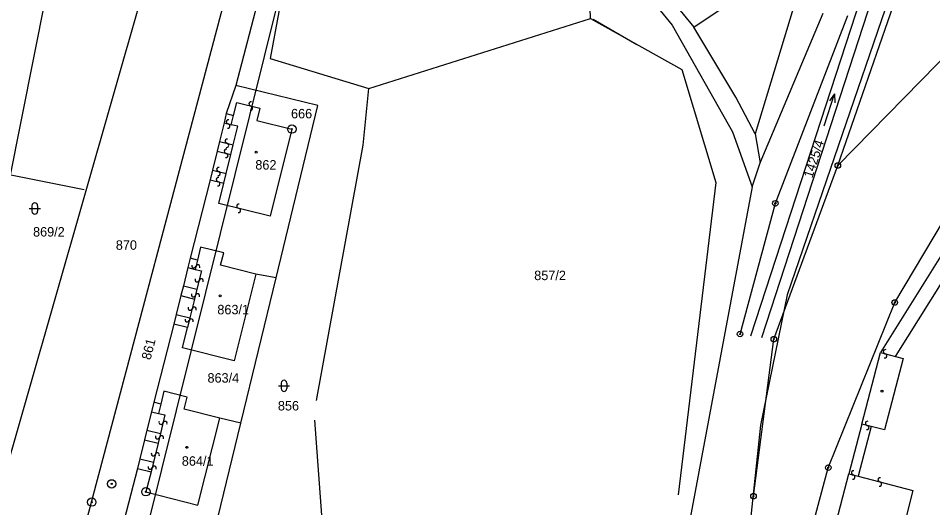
# Model space of a CAD drawing. Extents: x -469926 to -462499, y -1098642 to -1092733.
# Drawn here: x -465754.8 to -465590.7, y -1094948.2 to -1094860.4 of the extents above; entities that cross this region are included whole.
import ezdxf

# ---------------------------------------------------------------- set-up
doc = ezdxf.new("R2010")
doc.units = 0
for name, color, linetype in [('Vrstva 1', 7, 'Continuous'), ('Vrstva 14', 7, 'Continuous'), ('Vrstva 24', 7, 'Continuous'), ('Vrstva 25', 7, 'Continuous'), ('Vrstva 27', 7, 'Continuous'), ('Vrstva 4', 7, 'Continuous'), ('Vrstva 50', 7, 'Continuous'), ('Vrstva 51', 7, 'Continuous'), ('Vrstva 6', 7, 'Continuous'), ('Vrstva 63', 7, 'Continuous')]:
    doc.layers.add(name, color=color, linetype=linetype)

msp = doc.modelspace()

# ---------------------------------------------------------------- linework, layer by layer
at = {"layer": 'Vrstva 1'}
for p, q in [((-465698.22, -1094805.73), (-465715.79, -1094872.42)), ((-465698.22, -1094805.73), (-465709.61, -1094867.57)), ((-465705.26, -1094809.85), (-465747.5, -1094968.95)), ((-465774.7, -1094981.18), (-465741.64, -1094815.03)), ((-465727.35, -1094837.65), (-465765.18, -1094969.7)), ((-465652.11, -1094860.36), (-465652.54, -1094842.94)), ((-465652.54, -1094842.94), (-465637.41, -1094861.6)), ((-465648.71, -1094843.31), (-465633.53, -1094861.97)), ((-465607.69, -1094886.76), (-465568.94, -1094847.26)), ((-465613.05, -1094849.65), (-465622.51, -1094881.1)), ((-465607.69, -1094886.76), (-465595.39, -1094851.35)), ((-465633.53, -1094861.97), (-465624.18, -1094855.62)), ((-465621.65, -1094886.26), (-465610.33, -1094859.42)), ((-465691.88, -1094872.95), (-465652.11, -1094860.36)), ((-465652.11, -1094860.36), (-465635.72, -1094869.53)), ((-465618.91, -1094893.55), (-465605.92, -1094859.84)), ((-465637.41, -1094861.6), (-465626.59, -1094880.71)), ((-465626, -1094874.53), (-465633.53, -1094861.97)), ((-465709.61, -1094867.57), (-465691.88, -1094872.95)), ((-465635.72, -1094869.53), (-465629.58, -1094889.81)), ((-465715.79, -1094872.42), (-465717.48, -1094877.46)), ((-465701.04, -1094876), (-465715.79, -1094872.42)), ((-465692.94, -1094883.14), (-465691.88, -1094872.95)), ((-465692.94, -1094883.14), (-465691.88, -1094872.95)), ((-465622.51, -1094881.1), (-465626, -1094874.53)), ((-465717.48, -1094877.46), (-465717.88, -1094879.14)), ((-465708.56, -1094906.93), (-465701.04, -1094876)), ((-465717.88, -1094879.14), (-465718.69, -1094882.45)), ((-465626.59, -1094880.71), (-465623.08, -1094890.59)), ((-465718.69, -1094882.45), (-465719.12, -1094884.2)), ((-465622.51, -1094881.1), (-465621.65, -1094886.26)), ((-465701.3, -1094928.96), (-465692.94, -1094883.14)), ((-465719.12, -1094884.2), (-465719.94, -1094887.59)), ((-465619.18, -1094917.94), (-465607.69, -1094886.76)), ((-465719.94, -1094887.59), (-465720.36, -1094889.33)), ((-465720.36, -1094889.33), (-465723.95, -1094903.41)), ((-465629.58, -1094889.81), (-465636.35, -1094945.88)), ((-465623.08, -1094890.59), (-465634.59, -1094952.18)), ((-465597.47, -1094911.35), (-465584.24, -1094889.14)), ((-465625.24, -1094917.01), (-465618.91, -1094893.55)), ((-465722.1, -1094901.44), (-465722.66, -1094903.73)), ((-465717.95, -1094902.44), (-465722.1, -1094901.44)), ((-465723.95, -1094903.41), (-465724.37, -1094905.08)), ((-465722.66, -1094903.73), (-465723.95, -1094903.41)), ((-465718.51, -1094904.64), (-465717.95, -1094902.44)), ((-465724.37, -1094905.08), (-465725.19, -1094908.38)), ((-465712.19, -1094906.26), (-465718.51, -1094904.64)), ((-465712.19, -1094906.26), (-465716.1, -1094921.83)), ((-465714.9, -1094933.02), (-465708.56, -1094906.93)), ((-465708.56, -1094906.93), (-465712.19, -1094906.26)), ((-465725.19, -1094908.38), (-465725.62, -1094910.12)), ((-465725.62, -1094910.12), (-465726.46, -1094913.49)), ((-465609.41, -1094941), (-465597.47, -1094911.35)), ((-465726.46, -1094913.49), (-465726.89, -1094915.23)), ((-465726.89, -1094915.23), (-465730.52, -1094929.27)), ((-465724.46, -1094915.83), (-465726.89, -1094915.23)), ((-465725.37, -1094919.47), (-465724.46, -1094915.83)), ((-465622.83, -1094946.11), (-465619.18, -1094917.94)), ((-465716.1, -1094921.83), (-465725.37, -1094919.47)), ((-465728.67, -1094927.29), (-465729.25, -1094929.58)), ((-465724.52, -1094928.32), (-465728.67, -1094927.29)), ((-465725.06, -1094930.52), (-465724.52, -1094928.32)), ((-465730.52, -1094929.27), (-465730.93, -1094930.95)), ((-465729.25, -1094929.58), (-465730.52, -1094929.27)), ((-465730.93, -1094930.95), (-465731.73, -1094934.27)), ((-465718.67, -1094932.13), (-465725.06, -1094930.52)), ((-465722.6, -1094947.71), (-465718.67, -1094932.13)), ((-465721.21, -1094959.01), (-465714.9, -1094933.02)), ((-465714.9, -1094933.02), (-465718.67, -1094932.13)), ((-465698.71, -1094971.07), (-465701.56, -1094932.5)), ((-465731.73, -1094934.27), (-465732.16, -1094936.02)), ((-465732.16, -1094936.02), (-465732.98, -1094939.4)), ((-465732.98, -1094939.4), (-465733.4, -1094941.14)), ((-465733.4, -1094941.14), (-465737.05, -1094955.16)), ((-465733.4, -1094941.14), (-465730.97, -1094941.73)), ((-465613.36, -1094955.68), (-465609.41, -1094941)), ((-465730.97, -1094941.73), (-465731.92, -1094945.33)), ((-465731.92, -1094945.33), (-465722.6, -1094947.71))]:
    msp.add_line(p, q, dxfattribs=at)
at = {"layer": 'Vrstva 14'}
msp.add_line((-465687.49, -1094773.7), (-465736.67, -1094971.8), dxfattribs=at)
at = {"layer": 'Vrstva 24'}
for centre, radius in [((-465705.7, -1094880.23), 0.75), ((-465705.7, -1094880.23), 0.1), ((-465607.69, -1094886.76), 0.5), ((-465607.69, -1094886.76), 0.1), ((-465618.91, -1094893.55), 0.5), ((-465618.91, -1094893.55), 0.1), ((-465597.47, -1094911.35), 0.5), ((-465597.47, -1094911.35), 0.1), ((-465625.24, -1094917.01), 0.5), ((-465625.24, -1094917.01), 0.1), ((-465619.18, -1094917.94), 0.5), ((-465619.18, -1094917.94), 0.1), ((-465609.41, -1094941), 0.5), ((-465609.41, -1094941), 0.1), ((-465738.06, -1094943.9), 0.75), ((-465738.06, -1094943.9), 0.1), ((-465731.92, -1094945.33), 0.75), ((-465741.64, -1094947.18), 0.75), ((-465731.92, -1094945.33), 0.1), ((-465622.83, -1094946.11), 0.5), ((-465622.83, -1094946.11), 0.1), ((-465741.64, -1094947.18), 0.1)]:
    msp.add_circle(centre, radius, dxfattribs=at)
at = {"layer": 'Vrstva 25'}
for p, q in [((-465752.37, -1094893.98), (-465752.37, -1094894.98)), ((-465751.37, -1094893.98), (-465751.37, -1094894.98)), ((-465752.87, -1094894.48), (-465750.87, -1094894.48)), ((-465708.12, -1094926.31), (-465706.12, -1094926.31)), ((-465707.62, -1094925.81), (-465707.62, -1094926.81)), ((-465706.62, -1094925.81), (-465706.62, -1094926.81))]:
    msp.add_line(p, q, dxfattribs=at)
for points in [[(-465610.12, -1094879.62), (-465608.26, -1094873.92), (-465609.2, -1094875.19)], [(-465608.26, -1094873.92), (-465608.25, -1094875.5)]]:
    msp.add_lwpolyline(points, dxfattribs=at)
for centre in [(-465712.1, -1094884.35), (-465718.59, -1094910.17), (-465599.76, -1094927.27), (-465724.59, -1094937.35)]:
    msp.add_circle(centre, 0.175, dxfattribs=at)
for centre, start, end in [((-465751.87, -1094893.98), 0, 180), ((-465751.87, -1094894.98), 180, 0), ((-465707.12, -1094925.81), 0, 180), ((-465707.12, -1094926.81), 180, 0)]:
    msp.add_arc(centre, 0.5, start, end, dxfattribs=at)
at = {"layer": 'Vrstva 27'}
msp.add_lwpolyline([(-465743.02, -1094891.12), (-465797.45, -1094880.27)], dxfattribs=at)
at = {"layer": 'Vrstva 4'}
for p, q in [((-465623.29, -1094917.31), (-465601.6, -1094850.75)), ((-465621.33, -1094917.61), (-465599.61, -1094850.95)), ((-465716.18, -1094877.77), (-465715.62, -1094875.48)), ((-465715.62, -1094875.48), (-465711.46, -1094876.49)), ((-465717.48, -1094877.46), (-465716.18, -1094877.77)), ((-465711.46, -1094876.49), (-465712.02, -1094878.67)), ((-465717.88, -1094879.14), (-465716.59, -1094879.46)), ((-465716.59, -1094879.46), (-465716.18, -1094877.77)), ((-465712.02, -1094878.67), (-465705.7, -1094880.23)), ((-465715.44, -1094879.73), (-465716.59, -1094879.46)), ((-465716.25, -1094883.05), (-465715.44, -1094879.73)), ((-465705.7, -1094880.23), (-465709.59, -1094895.87)), ((-465718.69, -1094882.45), (-465716.25, -1094883.05)), ((-465716.67, -1094884.8), (-465716.25, -1094883.05)), ((-465719.12, -1094884.2), (-465716.67, -1094884.8)), ((-465717.5, -1094888.18), (-465716.67, -1094884.8)), ((-465623.08, -1094890.59), (-465621.65, -1094886.26)), ((-465719.94, -1094887.59), (-465717.5, -1094888.18)), ((-465717.92, -1094889.92), (-465717.5, -1094888.18)), ((-465720.36, -1094889.33), (-465717.92, -1094889.92)), ((-465718.82, -1094893.57), (-465717.92, -1094889.92)), ((-465709.59, -1094895.87), (-465718.82, -1094893.57)), ((-465586.52, -1094898.68), (-465600.01, -1094920.35)), ((-465597.31, -1094921.05), (-465584.87, -1094901.09)), ((-465722.66, -1094903.73), (-465723.08, -1094905.41)), ((-465724.37, -1094905.08), (-465723.08, -1094905.41)), ((-465723.08, -1094905.41), (-465721.94, -1094905.69)), ((-465721.94, -1094905.69), (-465722.76, -1094908.99)), ((-465725.19, -1094908.38), (-465722.76, -1094908.99)), ((-465725.62, -1094910.12), (-465723.19, -1094910.73)), ((-465722.76, -1094908.99), (-465723.19, -1094910.73)), ((-465723.19, -1094910.73), (-465724.03, -1094914.1)), ((-465726.46, -1094913.49), (-465724.03, -1094914.1)), ((-465724.03, -1094914.1), (-465724.46, -1094915.83)), ((-465603.38, -1094933.17), (-465600.01, -1094920.35)), ((-465600.01, -1094920.35), (-465597.31, -1094921.05)), ((-465595.96, -1094921.41), (-465599.32, -1094934.23)), ((-465597.31, -1094921.05), (-465595.96, -1094921.41)), ((-465729.25, -1094929.58), (-465729.65, -1094931.26)), ((-465730.93, -1094930.95), (-465729.65, -1094931.26)), ((-465729.65, -1094931.26), (-465728.5, -1094931.54)), ((-465728.5, -1094931.54), (-465729.3, -1094934.86)), ((-465603.38, -1094933.17), (-465605.7, -1094942.11)), ((-465601.71, -1094933.6), (-465603.38, -1094933.17)), ((-465731.73, -1094934.27), (-465729.3, -1094934.86)), ((-465729.3, -1094934.86), (-465729.73, -1094936.61)), ((-465601.71, -1094933.6), (-465604.05, -1094942.54)), ((-465599.32, -1094934.23), (-465601.71, -1094933.6)), ((-465732.16, -1094936.02), (-465729.73, -1094936.61)), ((-465729.73, -1094936.61), (-465730.55, -1094939.99)), ((-465732.98, -1094939.4), (-465730.55, -1094939.99)), ((-465730.55, -1094939.99), (-465730.97, -1094941.73)), ((-465616.37, -1094982.77), (-465605.7, -1094942.11)), ((-465605.7, -1094942.11), (-465604.05, -1094942.54)), ((-465604.05, -1094942.54), (-465594.2, -1094945.11)), ((-465594.2, -1094945.11), (-465595.36, -1094949.57))]:
    msp.add_line(p, q, dxfattribs=at)
at = {"layer": 'Vrstva 51'}
for centre, radius, start, end in [((-465713.06, -1094875.72), 0.376, 77.9904, 264.3015), ((-465713.13, -1094876.47), 0.377, 257.3143, 84.9775), ((-465717.12, -1094878.94), 0.376, 77.9904, 264.3015), ((-465717.2, -1094879.69), 0.377, 257.3143, 84.9775), ((-465717.34, -1094882.4), 0.376, 77.9904, 264.3015), ((-465717.47, -1094884.22), 0.376, 77.9904, 264.3015), ((-465717.41, -1094883.15), 0.377, 257.3143, 84.9775), ((-465717.54, -1094884.97), 0.377, 257.3143, 84.9775), ((-465718.86, -1094887.47), 0.376, 77.9904, 264.3015), ((-465718.92, -1094889.3), 0.376, 77.9904, 264.3015), ((-465718.93, -1094888.22), 0.377, 257.3143, 84.9775), ((-465718.99, -1094890.05), 0.377, 257.3143, 84.9775), ((-465715.23, -1094894.08), 0.376, 77.9904, 264.3015), ((-465715.3, -1094894.83), 0.377, 257.3143, 84.9775), ((-465723.31, -1094904.78), 0.376, 157.6504, 343.9615), ((-465722.59, -1094904.98), 0.377, 336.9743, 164.6375), ((-465722.72, -1094907.28), 0.376, 157.6504, 343.9615), ((-465722, -1094907.49), 0.377, 336.9743, 164.6375), ((-465723.39, -1094909.97), 0.376, 157.6504, 343.9615), ((-465722.67, -1094910.18), 0.377, 336.9743, 164.6375), ((-465723.98, -1094912.36), 0.376, 157.6504, 343.9615), ((-465723.26, -1094912.57), 0.377, 336.9743, 164.6375), ((-465724.51, -1094914.48), 0.376, 157.6504, 343.9615), ((-465723.79, -1094914.68), 0.377, 336.9743, 164.6375), ((-465599.16, -1094920.18), 0.376, 76.4004, 262.7115), ((-465599.25, -1094920.93), 0.377, 255.7243, 83.3875), ((-465729.2, -1094932.86), 0.376, 157.6504, 343.9615), ((-465728.48, -1094933.06), 0.377, 336.9743, 164.6375), ((-465602.37, -1094933.04), 0.376, 76.4004, 262.7115), ((-465602.46, -1094933.79), 0.377, 255.7243, 83.3875), ((-465729.83, -1094935.45), 0.376, 157.6504, 343.9615), ((-465729.11, -1094935.65), 0.377, 336.9743, 164.6375), ((-465729.86, -1094938.72), 0.377, 336.9743, 164.6375), ((-465730.58, -1094938.52), 0.376, 157.6504, 343.9615), ((-465731.16, -1094940.91), 0.376, 157.6504, 343.9615), ((-465730.43, -1094941.11), 0.377, 336.9743, 164.6375), ((-465604.89, -1094941.94), 0.376, 76.4004, 262.7115), ((-465604.98, -1094942.68), 0.377, 255.7243, 83.3875), ((-465600.11, -1094943.18), 0.376, 76.4004, 262.7115), ((-465600.2, -1094943.93), 0.377, 255.7243, 83.3875)]:
    msp.add_arc(centre, radius, start, end, dxfattribs=at)
at = {"layer": 'Vrstva 6'}
for p, q in [((-465598.28, -1094855.98), (-465616.76, -1094909.97)), ((-465616.76, -1094909.97), (-465621.58, -1094933.34)), ((-465621.58, -1094933.34), (-465626.4, -1094979.28))]:
    msp.add_line(p, q, dxfattribs=at)
at = {"layer": 'Vrstva 63'}
msp.add_lwpolyline([(-465651.64, -1094860.52), (-465643.79, -1094865.03)], dxfattribs=at)

# ---------------------------------------------------------------- texts
at = {"layer": 'Vrstva 50'}
for s, p in [('666', (-465705.86, -1094878.31)), ('862', (-465712.27, -1094887.5)), ('869/2', (-465752.18, -1094899.52)), ('870', (-465737.32, -1094901.89)), ('857/2', (-465662.2, -1094907.34)), ('863/1', (-465719.09, -1094913.48)), ('863/4', (-465720.86, -1094925.74)), ('856', (-465708.22, -1094930.73)), ('864/1', (-465725.47, -1094940.65))]:
    msp.add_text(s, height=1.7, dxfattribs=at).set_placement(p)
for s, rotation, p in [('1425/4', 72.018, (-465612.27, -1094889.14)), ('861', 75.573, (-465731.1, -1094921.76))]:
    msp.add_text(s, height=1.7, rotation=rotation, dxfattribs=at).set_placement(p)

doc.saveas('drawing.dxf')
